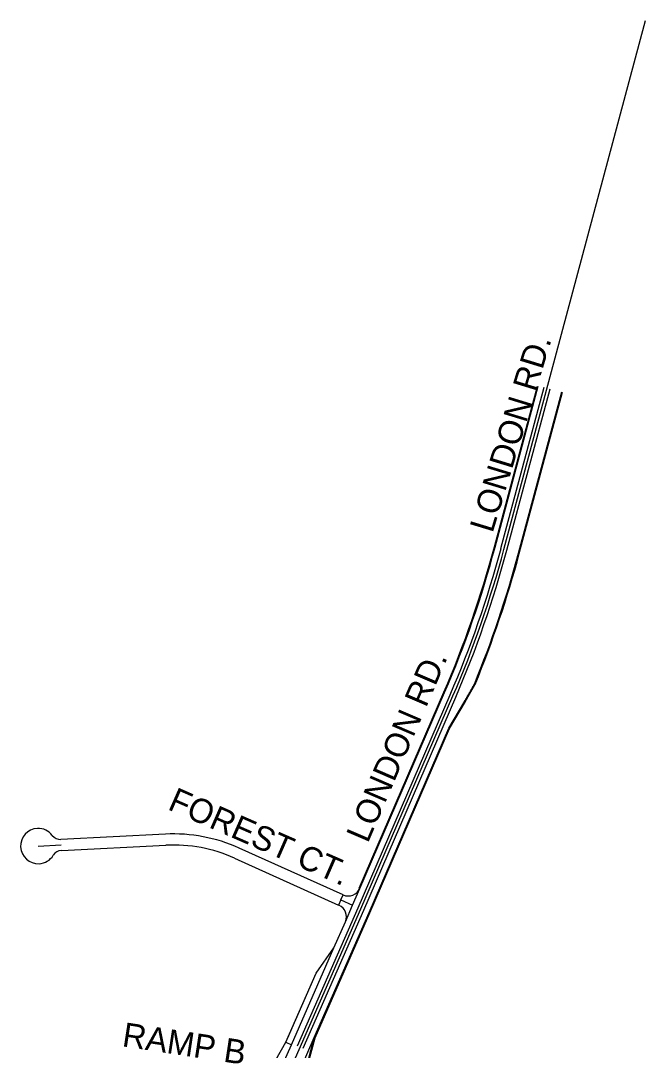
# Model space of a CAD drawing. Extents: x 2315515 to 2326910, y 758186 to 762794.
# Drawn here: x 2320679 to 2321918, y 760752 to 762794 of the extents above; entities that cross this region are included whole.
import ezdxf

# ---------------------------------------------------------------- set-up
doc = ezdxf.new("R2010")
doc.units = 0
for name, color, linetype in [('Default', 7, 'Continuous'), ('Draft_Corr_Range_Final', 7, 'Continuous'), ('E_Terrain_Exterior', 7, 'Continuous'), ('Level 0', 7, 'Continuous'), ('Pavement Marking Yellow', 7, 'Continuous'), ('Road_Curb_Face', 7, 'Continuous'), ('TL_End Condition Ditch In', 7, 'Continuous'), ('TL_End Condition Ditch Out', 7, 'Continuous')]:
    doc.layers.add(name, color=color, linetype=linetype)

msp = doc.modelspace()

# ---------------------------------------------------------------- linework, layer by layer
at = {"layer": 'Default'}
for p, q in [((2321637, 761745.2), (2321917.6, 762793.6)), ((2321637, 761745.2), (2321917.6, 762793.6)), ((2321637, 761745.2), (2321917.6, 762793.6)), ((2321353.4, 761032.3), (2321535.9, 761454.5)), ((2321353.4, 761032.3), (2321535.9, 761454.5)), ((2321353.4, 761032.3), (2321535.9, 761454.5)), ((2320896.6, 759992.2), (2321353.4, 761032.3)), ((2320896.6, 759992.2), (2321353.4, 761032.3)), ((2320896.6, 759992.2), (2321353.4, 761032.3))]:
    msp.add_line(p, q, dxfattribs=at)
msp.add_arc((2319608.4, 762288), 2100, 336.617, 345.0204, dxfattribs=at)
msp.add_arc((2319608.4, 762288), 2100, 336.617, 345.0204, dxfattribs=at)
msp.add_arc((2319608.4, 762288), 2100, 336.617, 345.0204, dxfattribs=at)
msp.add_open_spline([(2321559.3, 761444.4), (2321559.6, 761445), (2321560.3, 761446.1), (2321561.2, 761447.8), (2321562.2, 761449.5), (2321563.2, 761451.2), (2321564.1, 761452.9), (2321565.1, 761454.5), (2321566.1, 761456.2), (2321567, 761457.9), (2321568, 761459.6), (2321569, 761461.3), (2321569.9, 761463), (2321570.9, 761464.7), (2321571.8, 761466.4), (2321572.8, 761468.1), (2321573.7, 761469.7), (2321574.7, 761471.4), (2321575.6, 761473.1), (2321576.6, 761474.8), (2321577.5, 761476.5), (2321578.2, 761477.7), (2321578.5, 761478.2)], degree=3, dxfattribs=at)
at = {"layer": 'Draft_Corr_Range_Final'}
msp.add_line((2321215.5, 760763.1), (2321299.9, 760955.4), dxfattribs=at)
at = {"layer": 'E_Terrain_Exterior'}
for p, q in [((2321619.7, 761749.8), (2321705, 762068.7)), ((2321619.7, 761749.8), (2321705, 762068.7)), ((2321666, 761737.4), (2321751.6, 762057.4)), ((2321666, 761737.4), (2321751.6, 762057.4)), ((2321351.4, 761073.1), (2321519.4, 761461.7)), ((2321351.4, 761073.1), (2321519.4, 761461.7)), ((2321527.9, 761390.6), (2321559.3, 761444.4)), ((2321527.9, 761390.6), (2321559.3, 761444.4)), ((2321369.9, 761025.1), (2321527.9, 761390.6)), ((2321369.9, 761025.1), (2321527.9, 761390.6)), ((2320965.7, 761180.6), (2320758.4, 761170.3)), ((2320965.7, 761180.6), (2320758.4, 761170.3)), ((2320759.5, 761148.3), (2320966.8, 761158.6)), ((2321318.2, 761060.2), (2321112, 761153)), ((2321318.2, 761060.2), (2321112, 761153)), ((2321102.9, 761132.9), (2321309.2, 761040.1)), ((2321313.7, 761050.2), (2321318.2, 761060.2)), ((2321313.7, 761050.2), (2321309.2, 761040.1)), ((2321309.9, 761039.8), (2321309.2, 761040.1)), ((2321261, 760777.3), (2321369.9, 761025.1)), ((2321261, 760777.3), (2321369.9, 761025.1)), ((2321299.9, 760955.4), (2321322.6, 761006.9)), ((2321299.9, 760955.4), (2321322.6, 761006.9)), ((2321264.8, 760905.3), (2321299.9, 760955.4)), ((2321204.5, 760767.9), (2321264.8, 760905.3)), ((2321207.9, 760775.6), (2321264.8, 760905.3)), ((2321248.3, 760728.3), (2321261, 760777.3)), ((2321184.8, 760732.9), (2321204.5, 760767.9))]:
    msp.add_line(p, q, dxfattribs=at)
for centre, radius, start, end in [((2319608.4, 762288), 2082, 336.617, 345.0204), ((2319608.4, 762288), 2082, 336.617, 345.0204), ((2319608.4, 762288), 2130, 337.6565, 345.0204), ((2319608.4, 762288), 2130, 337.6565, 345.0204), ((2320713.6, 761157), 35, 92.8425, 272.8425), ((2320713.6, 761157), 35, 37.1502, 92.8425), ((2320757.4, 761190.2), 20, 217.1502, 272.8425), ((2320757.4, 761190.2), 20, 217.1502, 272.8425), ((2320981.5, 760863), 318, 65.781, 92.8425), ((2320981.5, 760863), 318, 65.781, 92.8425), ((2320760.5, 761128.3), 20, 92.8425, 148.5349), ((2320760.5, 761128.3), 20, 92.8425, 148.5349), ((2320981.5, 760863), 296, 65.781, 92.8425), ((2320713.6, 761157), 35, 272.8425, 328.5349), ((2321328.4, 761083), 25, 245.781, 336.617), ((2321299.7, 761017), 25, 336.2923, 65.781), ((2321299.7, 761017), 25, 336.2923, 65.781)]:
    msp.add_arc(centre, radius, start, end, dxfattribs=at)
msp.add_open_spline([(2321559.3, 761444.4), (2321559.6, 761445), (2321560.3, 761446.1), (2321561.2, 761447.8), (2321562.2, 761449.5), (2321563.2, 761451.2), (2321564.1, 761452.9), (2321565.1, 761454.5), (2321566.1, 761456.2), (2321567, 761457.9), (2321568, 761459.6), (2321569, 761461.3), (2321569.9, 761463), (2321570.9, 761464.7), (2321571.8, 761466.4), (2321572.8, 761468.1), (2321573.7, 761469.7), (2321574.7, 761471.4), (2321575.6, 761473.1), (2321576.6, 761474.8), (2321577.5, 761476.5), (2321578.2, 761477.7), (2321578.5, 761478.2)], degree=3, dxfattribs=at)
at = {"layer": 'Level 0'}
msp.add_line((2320713.6, 761157), (2320713.6, 761157), dxfattribs=at)
at = {"layer": 'Pavement Marking Yellow'}
for p, q in [((2321631.2, 761746.7), (2321716.9, 762066.7)), ((2321642.8, 761743.6), (2321728.5, 762063.6)), ((2321347.9, 761034.7), (2321530.4, 761456.9)), ((2321358.9, 761029.9), (2321541.4, 761452.2)), ((2321227.8, 760761.2), (2321347.9, 761034.7)), ((2321238.8, 760756.5), (2321358.9, 761029.9))]:
    msp.add_line(p, q, dxfattribs=at)
for radius in [2094, 2106]:
    msp.add_arc((2319608.4, 762288), radius, 336.617, 345.0204, dxfattribs=at)
at = {"layer": 'Road_Curb_Face'}
for p, q in [((2321618.2, 761750.2), (2321703.5, 762069.1)), ((2321667.5, 761737), (2321753.1, 762057)), ((2321667.5, 761737), (2321753.1, 762057)), ((2321579.8, 761477.5), (2321579.8, 761477.6)), ((2321350, 761073.7), (2321518, 761462.3)), ((2321529.2, 761389.8), (2321560.6, 761443.7)), ((2321529.2, 761389.9), (2321560.6, 761443.7)), ((2321371.3, 761024.5), (2321529.3, 761390)), ((2321371.3, 761024.5), (2321529.2, 761389.9)), ((2321262.4, 760776.7), (2321371.3, 761024.5)), ((2321262.5, 760776.8), (2321371.3, 761024.5)), ((2321249.7, 760727.9), (2321262.5, 760776.9)), ((2321249.7, 760727.9), (2321262.5, 760776.8))]:
    msp.add_line(p, q, dxfattribs=at)
for radius, start in [(2080.5, 336.617), (2131.5, 337.6542), (2131.5, 337.6565)]:
    msp.add_arc((2319608.4, 762288), radius, start, 345.0204, dxfattribs=at)
msp.add_open_spline([(2321560.6, 761443.7), (2321560.8, 761444), (2321561.4, 761445.1), (2321562.6, 761447.1), (2321563.5, 761448.7), (2321564.5, 761450.4), (2321565.4, 761452.1), (2321566.4, 761453.8), (2321567.4, 761455.5), (2321568.3, 761457.2), (2321569.3, 761458.9), (2321570.3, 761460.6), (2321571.2, 761462.2), (2321572.2, 761463.9), (2321573.1, 761465.6), (2321574.1, 761467.3), (2321575.1, 761469), (2321576, 761470.7), (2321577, 761472.4), (2321577.9, 761474), (2321579, 761476.1), (2321579.6, 761477.2), (2321579.8, 761477.5)], degree=2, dxfattribs=at)
msp.add_open_spline([(2321560.6, 761443.7), (2321560.8, 761444), (2321561.4, 761445.1), (2321562.6, 761447.1), (2321563.5, 761448.7), (2321564.5, 761450.4), (2321565.4, 761452.1), (2321566.4, 761453.8), (2321567.4, 761455.5), (2321568.3, 761457.2), (2321569.3, 761458.9), (2321570.3, 761460.6), (2321571.2, 761462.2), (2321572.2, 761463.9), (2321573.1, 761465.6), (2321574.1, 761467.3), (2321575.1, 761469), (2321576, 761470.7), (2321577, 761472.4), (2321577.9, 761474), (2321579, 761476.1), (2321579.6, 761477.2), (2321579.8, 761477.5)], degree=2, dxfattribs=at)
at = {"layer": 'TL_End Condition Ditch In'}
for p, q in [((2321336.9, 761039.5), (2321351.4, 761073.1)), ((2321313.7, 761050.2), (2321337, 761039.7)), ((2321322.6, 761006.9), (2321336.9, 761039.5)), ((2321196.2, 760629.7), (2321261, 760777.3)), ((2321163, 760643.5), (2321215.5, 760763.1)), ((2321204.5, 760767.9), (2321215.5, 760763.1))]:
    msp.add_line(p, q, dxfattribs=at)
at = {"layer": 'TL_End Condition Ditch Out'}
msp.add_line((2320713.6, 761157), (2320759, 761159.3), dxfattribs=at)

# ---------------------------------------------------------------- texts
at = {"layer": 'Default'}
for s, rotation, p in [('LONDON RD.', 73.0343, (2321614.3, 761776.1)), ('LONDON RD.', 66.7465, (2321367, 761161.2)), ('FOREST CT.', 336.3217, (2320968.3, 761230.5)), ('RAMP B', 351.3639, (2320878.3, 760760.2))]:
    msp.add_text(s, height=48, rotation=rotation, dxfattribs=at).set_placement(p)

doc.saveas('drawing.dxf')
